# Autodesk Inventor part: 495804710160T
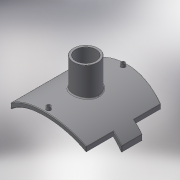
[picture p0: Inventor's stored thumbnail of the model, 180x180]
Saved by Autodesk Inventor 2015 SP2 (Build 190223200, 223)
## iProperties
Created: 2017-10
Part Number: 495804710160T
Material: Generic
Description: PLASSON BRANCH SADDLE 450-800X160
Document SubType Name: Modeling
Designer: KIM
Density: 1 g/cm^3
Appearance: Default
Author: KIM
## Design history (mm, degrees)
derived "495804 (SECOND).ipt"
feature "Solid1::495804 (SECOND).ipt"
tag "TaggingFeature1"
body "Solid1"
other parameters: "d1" = 15, "d2" = 283.5, "d4" = 0, "d5" = 315, "d6" = 75, "d7" = 0, "d8" = 135, "d10" = 0, "d11" = 4, "d12" = 425.6, "d13" = 14, "d14" = 135, "d16" = 5 deg, "d18" = 4, "d19" = 14, "d20" = 0, "d21" = 3, "d22" = 0, "d25" = 16, "d26" = 128, "d28" = 0, "d29" = 9.6, "d31" = 0, "d32" = 34.5, "d33" = 0, "d34" = 8, "d35" = 1.6, "B_" = 315, "H_" = 115, "x_" = 15, "D_" = 16
